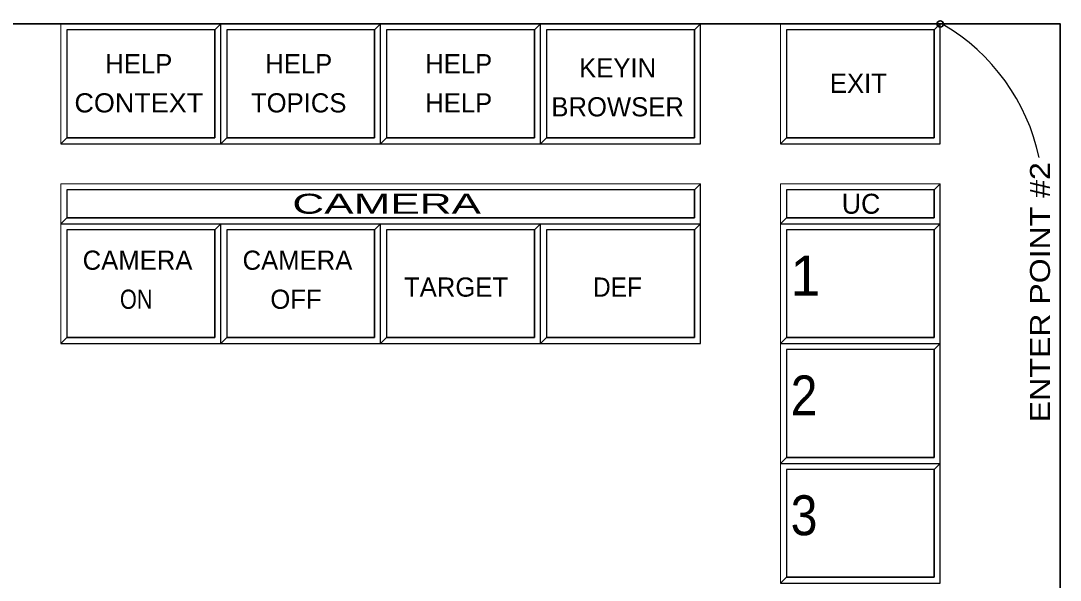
# Model space of a CAD drawing. Extents: x 95906.8 to 95923.6, y 90964.8 to 90972.8.
# Drawn here: x 95916.232 to 95918.832, y 90971.369 to 90972.77 of the extents above; entities that cross this region are included whole.
import ezdxf
from ezdxf.enums import TextEntityAlignment as Align

# ---------------------------------------------------------------- set-up
doc = ezdxf.new("R2010")
doc.units = 0
doc.header["$LTSCALE"] = 0.019
for name, color, linetype, lineweight in [('11', 7, 'Continuous', 25), ('12', 7, 'Continuous', 25), ('16', 7, 'Continuous', 25), ('18', 7, 'Continuous', 25), ('2', 7, 'Continuous', 13), ('21', 7, 'Continuous', 25), ('3', 7, 'Continuous', 25), ('6', 7, 'Continuous', 25), ('7', 7, 'Continuous', 35)]:
    doc.layers.add(name, color=color, linetype=linetype, lineweight=lineweight)

msp = doc.modelspace()

# ---------------------------------------------------------------- linework, layer by layer
at = {"layer": '11'}
for points in [[(95916.3473, 90972.4767), (95916.7173, 90972.4767), (95916.7173, 90972.7467), (95916.3473, 90972.7467)], [(95916.7473, 90972.4767), (95917.1173, 90972.4767), (95917.1173, 90972.7467), (95916.7473, 90972.7467)], [(95917.1473, 90972.4767), (95917.5173, 90972.4767), (95917.5173, 90972.7467), (95917.1473, 90972.7467)], [(95917.5473, 90972.4767), (95917.9173, 90972.4767), (95917.9173, 90972.7467), (95917.5473, 90972.7467)], [(95917.1473, 90971.9767), (95917.5173, 90971.9767), (95917.5173, 90972.2467), (95917.1473, 90972.2467)], [(95917.5473, 90971.9767), (95917.9173, 90971.9767), (95917.9173, 90972.2467), (95917.5473, 90972.2467)], [(95918.1473, 90971.9767), (95918.5173, 90971.9767), (95918.5173, 90972.2467), (95918.1473, 90972.2467)], [(95918.1473, 90971.6767), (95918.5173, 90971.6767), (95918.5173, 90971.9467), (95918.1473, 90971.9467)], [(95918.1473, 90971.3767), (95918.5173, 90971.3767), (95918.5173, 90971.6467), (95918.1473, 90971.6467)]]:
    msp.add_lwpolyline(points, close=True, dxfattribs=at)
at = {"layer": '12'}
for points in [[(95916.3473, 90971.9767), (95916.7173, 90971.9767), (95916.7173, 90972.2467), (95916.3473, 90972.2467)], [(95916.7473, 90971.9767), (95917.1173, 90971.9767), (95917.1173, 90972.2467), (95916.7473, 90972.2467)]]:
    msp.add_lwpolyline(points, close=True, dxfattribs=at)
at = {"layer": '16'}
msp.add_lwpolyline([(95918.1473, 90972.4767), (95918.5173, 90972.4767), (95918.5173, 90972.7467), (95918.1473, 90972.7467)], close=True, dxfattribs=at)
at = {"layer": '18'}
msp.add_lwpolyline([(95918.1473, 90972.2767), (95918.5173, 90972.2767), (95918.5173, 90972.3467), (95918.1473, 90972.3467)], close=True, dxfattribs=at)
at = {"layer": '2'}
for points in [[(95916.3323, 90972.7617), (95916.3323, 90972.4617), (95916.3473, 90972.4767), (95916.3473, 90972.7467), (95916.7173, 90972.7467), (95916.7323, 90972.7617)], [(95916.7323, 90972.7617), (95916.7323, 90972.4617), (95916.7473, 90972.4767), (95916.7473, 90972.7467), (95917.1173, 90972.7467), (95917.1323, 90972.7617)], [(95917.1323, 90972.7617), (95917.1323, 90972.4617), (95917.1473, 90972.4767), (95917.1473, 90972.7467), (95917.5173, 90972.7467), (95917.5323, 90972.7617)], [(95917.5323, 90972.7617), (95917.5323, 90972.4617), (95917.5473, 90972.4767), (95917.5473, 90972.7467), (95917.9173, 90972.7467), (95917.9323, 90972.7617)], [(95918.1323, 90972.7617), (95918.1323, 90972.4617), (95918.1473, 90972.4767), (95918.1473, 90972.7467), (95918.5173, 90972.7467), (95918.5323, 90972.7617)], [(95916.3323, 90972.3617), (95916.3323, 90972.2617), (95916.3473, 90972.2767), (95916.3473, 90972.3467), (95917.9173, 90972.3467), (95917.9323, 90972.3617)], [(95918.1323, 90972.3617), (95918.1323, 90972.2617), (95918.1473, 90972.2767), (95918.1473, 90972.3467), (95918.5173, 90972.3467), (95918.5323, 90972.3617)], [(95916.3323, 90972.2617), (95916.3323, 90971.9617), (95916.3473, 90971.9767), (95916.3473, 90972.2467), (95916.7173, 90972.2467), (95916.7323, 90972.2617)], [(95916.7323, 90972.2617), (95916.7323, 90971.9617), (95916.7473, 90971.9767), (95916.7473, 90972.2467), (95917.1173, 90972.2467), (95917.1323, 90972.2617)], [(95917.1323, 90972.2617), (95917.1323, 90971.9617), (95917.1473, 90971.9767), (95917.1473, 90972.2467), (95917.5173, 90972.2467), (95917.5323, 90972.2617)], [(95917.5323, 90972.2617), (95917.5323, 90971.9617), (95917.5473, 90971.9767), (95917.5473, 90972.2467), (95917.9173, 90972.2467), (95917.9323, 90972.2617)], [(95918.1323, 90972.2617), (95918.1323, 90971.9617), (95918.1473, 90971.9767), (95918.1473, 90972.2467), (95918.5173, 90972.2467), (95918.5323, 90972.2617)], [(95918.1323, 90971.9617), (95918.1323, 90971.6617), (95918.1473, 90971.6767), (95918.1473, 90971.9467), (95918.5173, 90971.9467), (95918.5323, 90971.9617)], [(95918.1323, 90971.6617), (95918.1323, 90971.3617), (95918.1473, 90971.3767), (95918.1473, 90971.6467), (95918.5173, 90971.6467), (95918.5323, 90971.6617)]]:
    msp.add_lwpolyline(points, close=True, dxfattribs=at)
at = {"layer": '21'}
msp.add_lwpolyline([(95916.3473, 90972.2767), (95917.9173, 90972.2767), (95917.9173, 90972.3467), (95916.3473, 90972.3467)], close=True, dxfattribs=at)
at = {"layer": '3'}
for points in [[(95916.3323, 90972.4617), (95916.7323, 90972.4617), (95916.7323, 90972.7617), (95916.7173, 90972.7467), (95916.7173, 90972.4767), (95916.3473, 90972.4767)], [(95916.7323, 90972.4617), (95917.1323, 90972.4617), (95917.1323, 90972.7617), (95917.1173, 90972.7467), (95917.1173, 90972.4767), (95916.7473, 90972.4767)], [(95917.1323, 90972.4617), (95917.5323, 90972.4617), (95917.5323, 90972.7617), (95917.5173, 90972.7467), (95917.5173, 90972.4767), (95917.1473, 90972.4767)], [(95917.5323, 90972.4617), (95917.9323, 90972.4617), (95917.9323, 90972.7617), (95917.9173, 90972.7467), (95917.9173, 90972.4767), (95917.5473, 90972.4767)], [(95918.1323, 90972.4617), (95918.5323, 90972.4617), (95918.5323, 90972.7617), (95918.5173, 90972.7467), (95918.5173, 90972.4767), (95918.1473, 90972.4767)], [(95916.3323, 90972.2617), (95917.9323, 90972.2617), (95917.9323, 90972.3617), (95917.9173, 90972.3467), (95917.9173, 90972.2767), (95916.3473, 90972.2767)], [(95918.1323, 90972.2617), (95918.5323, 90972.2617), (95918.5323, 90972.3617), (95918.5173, 90972.3467), (95918.5173, 90972.2767), (95918.1473, 90972.2767)], [(95916.3323, 90971.9617), (95916.7323, 90971.9617), (95916.7323, 90972.2617), (95916.7173, 90972.2467), (95916.7173, 90971.9767), (95916.3473, 90971.9767)], [(95916.7323, 90971.9617), (95917.1323, 90971.9617), (95917.1323, 90972.2617), (95917.1173, 90972.2467), (95917.1173, 90971.9767), (95916.7473, 90971.9767)], [(95917.1323, 90971.9617), (95917.5323, 90971.9617), (95917.5323, 90972.2617), (95917.5173, 90972.2467), (95917.5173, 90971.9767), (95917.1473, 90971.9767)], [(95917.5323, 90971.9617), (95917.9323, 90971.9617), (95917.9323, 90972.2617), (95917.9173, 90972.2467), (95917.9173, 90971.9767), (95917.5473, 90971.9767)], [(95918.1323, 90971.9617), (95918.5323, 90971.9617), (95918.5323, 90972.2617), (95918.5173, 90972.2467), (95918.5173, 90971.9767), (95918.1473, 90971.9767)], [(95918.1323, 90971.6617), (95918.5323, 90971.6617), (95918.5323, 90971.9617), (95918.5173, 90971.9467), (95918.5173, 90971.6767), (95918.1473, 90971.6767)], [(95918.1323, 90971.3617), (95918.5323, 90971.3617), (95918.5323, 90971.6617), (95918.5173, 90971.6467), (95918.5173, 90971.3767), (95918.1473, 90971.3767)]]:
    msp.add_lwpolyline(points, close=True, dxfattribs=at)
at = {"layer": '7'}
msp.add_lwpolyline([(95906.8323, 90972.7617), (95918.8323, 90972.7617), (95918.8323, 90964.7617), (95906.8323, 90964.7617)], close=True, dxfattribs=at)
msp.add_circle((95918.5323, 90972.7617), 0.00808, dxfattribs=at)
at = {"layer": '7', "lineweight": 25}
msp.add_arc((95918.2789, 90972.3194), 0.5123, 12.1659, 59.4893, dxfattribs=at)

# ---------------------------------------------------------------- texts
at = {"layer": '21', "width": 1.65}
msp.add_text('         CAMERA        ', height=0.04999, dxfattribs=at).set_placement((95917.1322, 90972.2867), align=Align.CENTER)
at = {"layer": '6'}
for s, height, p in [('HELP', 0.048, (95916.5275, 90972.6383)), ('HELP', 0.048, (95916.9275, 90972.6383)), ('HELP', 0.048, (95917.3276, 90972.6383)), ('KEYIN', 0.04799, (95917.7252, 90972.6278)), ('EXIT', 0.048, (95918.3275, 90972.5893)), ('TOPICS', 0.048, (95916.9275, 90972.5403)), ('HELP', 0.048, (95917.3276, 90972.5403)), ('BROWSER', 0.04799, (95917.7252, 90972.5304)), ('CAMERA', 0.048, (95916.5244, 90972.1464)), ('CAMERA', 0.048, (95916.9244, 90972.1464)), ('TARGET', 0.048, (95917.3211, 90972.0791)), ('OFF', 0.048, (95916.9207, 90972.0487))]:
    msp.add_text(s, height=height, dxfattribs=at).set_placement(p, align=Align.CENTER)
for s, width, p in [('CONTEXT', 1.05, (95916.5275, 90972.5403)), ('DEF', 0.95, (95917.7248, 90972.0791)), ('ON', 0.85, (95916.5211, 90972.0487))]:
    msp.add_text(s, height=0.048, dxfattribs=dict(at, width=width)).set_placement(p, align=Align.CENTER)
msp.add_text('1', height=0.1, dxfattribs=at).set_placement((95918.1581, 90972.0818))
msp.add_text('1', height=0.1, dxfattribs=at).set_placement((95918.1581, 90972.0818))
at = {"layer": '6', "width": 0.9}
for s, p in [('2', (95918.1581, 90971.7818)), ('3', (95918.1581, 90971.4818))]:
    msp.add_text(s, height=0.1, dxfattribs=at).set_placement(p)
at = {"layer": '7', "width": 1.2}
msp.add_text('ENTER POINT #2', height=0.05, rotation=90, dxfattribs=at).set_placement((95918.8067, 90972.0903), align=Align.CENTER)
at = {"layer": '7'}
msp.add_text('UC', height=0.04999, dxfattribs=at).set_placement((95918.3341, 90972.2867), align=Align.CENTER)

doc.saveas('drawing.dxf')
